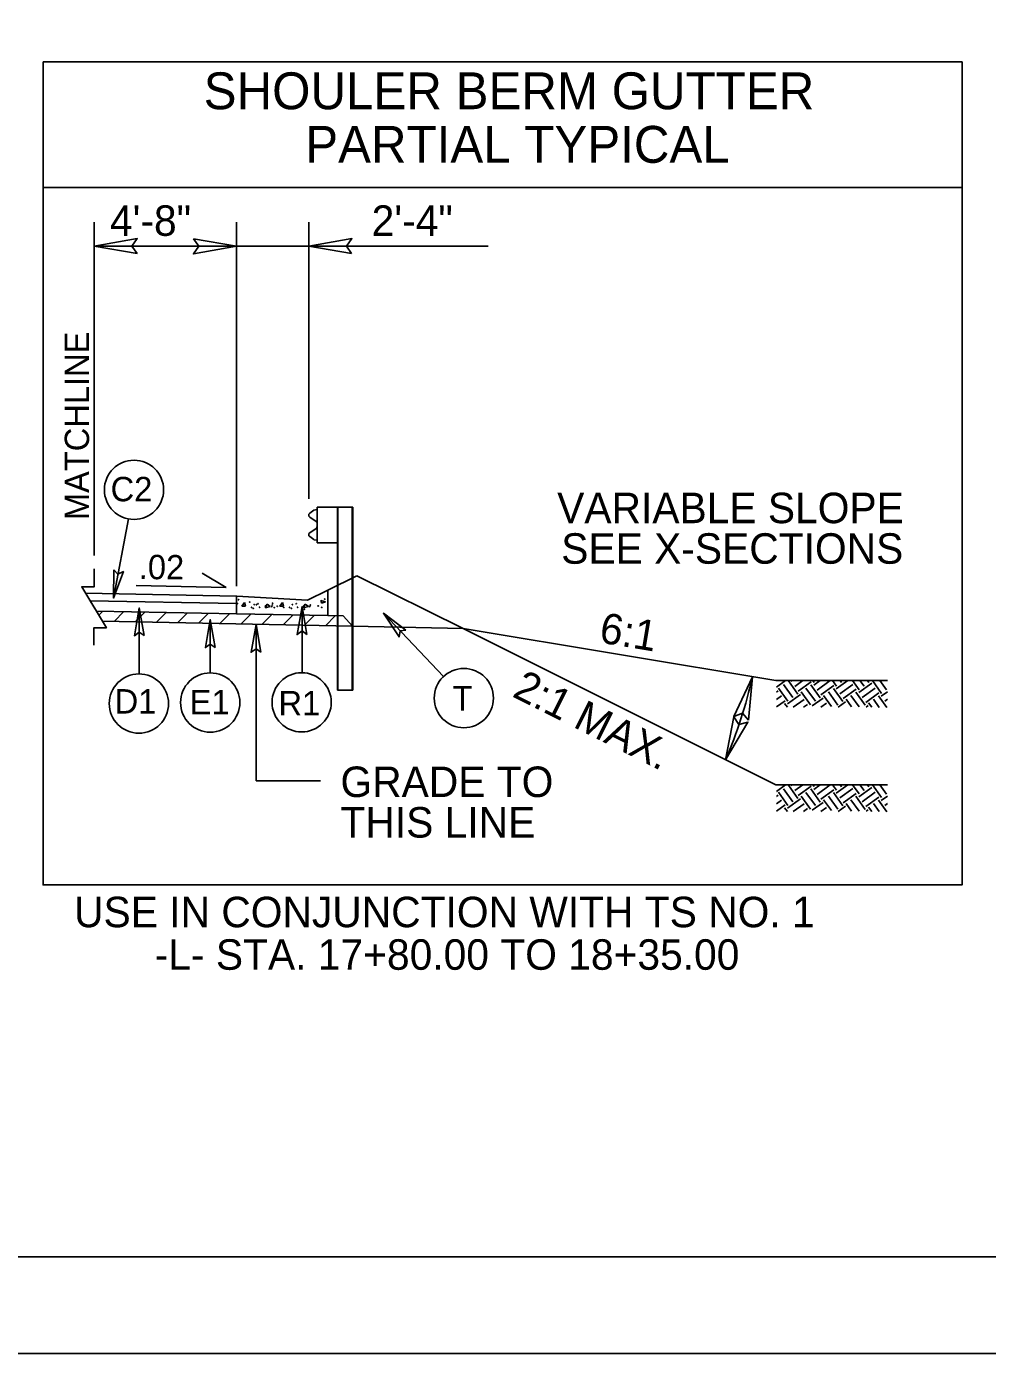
# Model space of a CAD drawing. Extents: x 1184121 to 1184397, y 1246506 to 1246661.
# Drawn here: x 1184220.23 to 1184251.75, y 1246505.71 to 1246549.22 of the extents above; entities that cross this region are included whole.
import ezdxf

# ---------------------------------------------------------------- set-up
doc = ezdxf.new("R2010")
doc.units = 0
for name, color, linetype in [('P_RDY_DXS_Guardrail_Cell', 7, 'Continuous'), ('Prop Shade Light', 7, 'Continuous'), ('Sheet Data Field CELL', 7, 'Continuous'), ('Sheet Plan CELL', 7, 'Continuous'), ('Sheet Plot Border Outside CELL', 7, 'Continuous'), ('Typical Text Label CELL', 7, 'Continuous'), ('z - Construction', 7, 'Continuous')]:
    doc.layers.add(name, color=color, linetype=linetype)

msp = doc.modelspace()

# ---------------------------------------------------------------- linework, layer by layer
at = {"layer": 'P_RDY_DXS_Guardrail_Cell'}
for p, q in [((1184229.654, 1246533.361), (1184229.517, 1246533.264)), ((1184229.754, 1246533.382), (1184229.667, 1246533.367)), ((1184230.427, 1246533.462), (1184229.76, 1246533.462)), ((1184229.76, 1246533.462), (1184229.76, 1246532.296)), ((1184230.427, 1246533.462), (1184230.927, 1246533.462)), ((1184230.443, 1246533.462), (1184230.427, 1246533.462)), ((1184230.427, 1246533.462), (1184230.427, 1246527.462)), ((1184230.443, 1246527.462), (1184230.443, 1246533.462)), ((1184230.927, 1246533.462), (1184230.911, 1246533.462)), ((1184230.911, 1246533.462), (1184230.911, 1246527.462)), ((1184230.927, 1246527.462), (1184230.927, 1246533.462)), ((1184229.518, 1246533.135), (1184229.726, 1246532.991)), ((1184229.76, 1246532.927), (1184229.76, 1246532.879)), ((1184229.76, 1246532.879), (1184229.76, 1246532.831)), ((1184229.517, 1246532.493), (1184229.654, 1246532.396)), ((1184229.726, 1246532.766), (1184229.518, 1246532.623)), ((1184229.667, 1246532.391), (1184229.754, 1246532.375)), ((1184229.76, 1246532.296), (1184230.427, 1246532.296)), ((1184230.427, 1246527.462), (1184230.927, 1246527.462)), ((1184230.427, 1246527.462), (1184230.443, 1246527.462)), ((1184230.911, 1246527.462), (1184230.927, 1246527.462))]:
    msp.add_line(p, q, dxfattribs=at)
for centre, radius, start, end in [((1184229.562, 1246533.2), 0.0787, 125.2976, 235.3478), ((1184229.673, 1246533.335), 0.0328, 100, 125.2976), ((1184229.681, 1246532.927), 0.0787, 0.02, 55.3478), ((1184229.681, 1246532.831), 0.0787, 304.6522, 359.98), ((1184229.562, 1246532.558), 0.0787, 124.6522, 234.7024), ((1184229.673, 1246532.423), 0.0328, 234.7024, 260)]:
    msp.add_arc(centre, radius, start, end, dxfattribs=at)
at = {"layer": 'Prop Shade Light'}
msp.add_lwpolyline([(1184227.114, 1246529.963), (1184222.518, 1246530.055), (1184222.315, 1246530.392), (1184227.109, 1246530.296), (1184227.114, 1246530.296)], close=True, dxfattribs=at)
at = {"layer": 'Sheet Data Field CELL'}
for p, q in [((1184222.447, 1246531.874), (1184222.447, 1246542.801)), ((1184227.114, 1246530.865), (1184227.114, 1246542.801)), ((1184229.484, 1246533.73), (1184229.484, 1246542.801)), ((1184222.447, 1246542.017), (1184227.114, 1246542.017)), ((1184227.114, 1246542.017), (1184235.365, 1246542.017)), ((1184223.079, 1246530.481), (1184223.574, 1246533.073)), ((1184226.776, 1246530.828), (1184225.993, 1246531.301)), ((1184231.065, 1246531.207), (1184230.114, 1246530.736)), ((1184231.065, 1246531.207), (1184234.553, 1246529.481)), ((1184222.163, 1246530.645), (1184227.114, 1246530.546)), ((1184226.776, 1246530.828), (1184223.822, 1246530.887)), ((1184229.447, 1246530.406), (1184230.114, 1246530.736)), ((1184230.114, 1246529.903), (1184230.114, 1246530.736)), ((1184222.315, 1246530.392), (1184227.109, 1246530.296)), ((1184227.114, 1246530.546), (1184227.114, 1246530.546)), ((1184227.114, 1246530.546), (1184227.114, 1246530.535)), ((1184227.114, 1246529.963), (1184227.114, 1246530.535)), ((1184227.125, 1246530.546), (1184229.447, 1246530.406)), ((1184227.292, 1246530.213), (1184227.378, 1246530.333)), ((1184227.412, 1246530.219), (1184227.292, 1246530.213)), ((1184227.378, 1246530.333), (1184227.412, 1246530.219)), ((1184228.057, 1246530.162), (1184228.12, 1246530.276)), ((1184228.223, 1246530.201), (1184228.057, 1246530.162)), ((1184228.12, 1246530.276), (1184228.223, 1246530.201)), ((1184228.541, 1246530.213), (1184228.627, 1246530.333)), ((1184228.661, 1246530.219), (1184228.541, 1246530.213)), ((1184228.627, 1246530.333), (1184228.661, 1246530.219)), ((1184229.265, 1246530.199), (1184229.265, 1246528.032)), ((1184229.306, 1246530.162), (1184229.368, 1246530.276)), ((1184229.471, 1246530.201), (1184229.306, 1246530.162)), ((1184229.368, 1246530.276), (1184229.471, 1246530.201)), ((1184229.884, 1246530.405), (1184229.9, 1246530.314)), ((1184230.038, 1246530.36), (1184229.884, 1246530.405)), ((1184229.9, 1246530.314), (1184230.038, 1246530.36)), ((1184222.518, 1246530.055), (1184227.114, 1246529.963)), ((1184222.599, 1246529.919), (1184222.73, 1246530.05)), ((1184223.096, 1246529.71), (1184223.423, 1246530.036)), ((1184223.79, 1246529.696), (1184224.116, 1246530.023)), ((1184223.926, 1246530.158), (1184223.926, 1246527.991)), ((1184224.483, 1246529.682), (1184224.809, 1246530.009)), ((1184225.176, 1246529.668), (1184225.503, 1246529.995)), ((1184225.869, 1246529.654), (1184226.196, 1246529.981)), ((1184226.253, 1246529.772), (1184226.253, 1246528.026)), ((1184226.563, 1246529.641), (1184226.889, 1246529.967)), ((1184230.114, 1246529.903), (1184227.114, 1246529.963)), ((1184227.256, 1246529.627), (1184227.582, 1246529.953)), ((1184227.949, 1246529.613), (1184228.276, 1246529.939)), ((1184228.642, 1246529.599), (1184228.969, 1246529.926)), ((1184229.336, 1246529.585), (1184229.662, 1246529.912)), ((1184230.029, 1246529.571), (1184230.356, 1246529.898)), ((1184230.114, 1246529.903), (1184230.614, 1246529.893)), ((1184230.614, 1246529.893), (1184230.923, 1246529.553)), ((1184231.934, 1246529.979), (1184233.903, 1246527.905)), ((1184222.72, 1246529.717), (1184230.923, 1246529.553)), ((1184227.754, 1246529.617), (1184227.754, 1246524.484)), ((1184230.923, 1246529.553), (1184234.553, 1246529.481)), ((1184234.553, 1246529.481), (1184244.81, 1246527.771)), ((1184234.553, 1246529.481), (1184244.81, 1246524.352)), ((1184244.81, 1246527.771), (1184248.464, 1246527.771)), ((1184244.81, 1246527.771), (1184248.464, 1246527.771)), ((1184244.824, 1246527.559), (1184245.119, 1246527.772)), ((1184244.824, 1246527.559), (1184245.119, 1246527.772)), ((1184245.364, 1246527.214), (1184245.055, 1246527.644)), ((1184245.364, 1246527.214), (1184245.055, 1246527.644)), ((1184245.525, 1246527.33), (1184245.216, 1246527.76)), ((1184245.525, 1246527.33), (1184245.216, 1246527.76)), ((1184245.308, 1246527.745), (1184245.347, 1246527.772)), ((1184245.308, 1246527.745), (1184245.347, 1246527.772)), ((1184245.424, 1246527.583), (1184245.688, 1246527.773)), ((1184245.424, 1246527.583), (1184245.688, 1246527.773)), ((1184245.54, 1246527.422), (1184245.969, 1246527.731)), ((1184245.54, 1246527.422), (1184245.969, 1246527.731)), ((1184246.263, 1246527.209), (1184245.954, 1246527.639)), ((1184246.263, 1246527.209), (1184245.954, 1246527.639)), ((1184246.062, 1246527.716), (1184246.02, 1246527.774)), ((1184246.062, 1246527.716), (1184246.02, 1246527.774)), ((1184246.047, 1246527.624), (1184246.257, 1246527.775)), ((1184246.047, 1246527.624), (1184246.257, 1246527.775)), ((1184246.162, 1246527.463), (1184246.592, 1246527.771)), ((1184246.162, 1246527.463), (1184246.592, 1246527.771)), ((1184246.278, 1246527.301), (1184246.708, 1246527.61)), ((1184246.278, 1246527.301), (1184246.708, 1246527.61)), ((1184246.8, 1246527.595), (1184246.67, 1246527.776)), ((1184246.8, 1246527.595), (1184246.67, 1246527.776)), ((1184246.785, 1246527.503), (1184247.168, 1246527.778)), ((1184246.785, 1246527.503), (1184247.168, 1246527.778)), ((1184246.901, 1246527.342), (1184247.331, 1246527.65)), ((1184246.901, 1246527.342), (1184247.331, 1246527.65)), ((1184246.961, 1246527.711), (1184246.914, 1246527.777)), ((1184246.961, 1246527.711), (1184246.914, 1246527.777)), ((1184247.539, 1246527.474), (1184247.325, 1246527.771)), ((1184247.539, 1246527.474), (1184247.325, 1246527.771)), ((1184247.523, 1246527.382), (1184247.953, 1246527.691)), ((1184247.523, 1246527.382), (1184247.953, 1246527.691)), ((1184247.7, 1246527.59), (1184247.564, 1246527.779)), ((1184247.7, 1246527.59), (1184247.564, 1246527.779)), ((1184247.861, 1246527.706), (1184247.814, 1246527.771)), ((1184247.861, 1246527.706), (1184247.814, 1246527.771)), ((1184248.277, 1246527.353), (1184247.977, 1246527.771)), ((1184248.277, 1246527.353), (1184247.977, 1246527.771)), ((1184248.438, 1246527.469), (1184248.221, 1246527.771)), ((1184248.438, 1246527.469), (1184248.221, 1246527.771)), ((1184244.824, 1246527.396), (1184244.879, 1246527.436)), ((1184244.824, 1246527.396), (1184244.879, 1246527.436)), ((1184244.824, 1246527.152), (1184244.994, 1246527.275)), ((1184244.824, 1246527.152), (1184244.994, 1246527.275)), ((1184245.202, 1246527.098), (1184244.894, 1246527.528)), ((1184245.202, 1246527.098), (1184244.894, 1246527.528)), ((1184245.187, 1246527.006), (1184245.617, 1246527.315)), ((1184245.187, 1246527.006), (1184245.617, 1246527.315)), ((1184245.375, 1246526.897), (1184245.733, 1246527.154)), ((1184245.375, 1246526.897), (1184245.733, 1246527.154)), ((1184245.941, 1246526.978), (1184245.632, 1246527.407)), ((1184245.941, 1246526.978), (1184245.632, 1246527.407)), ((1184246.102, 1246527.093), (1184245.793, 1246527.523)), ((1184246.102, 1246527.093), (1184245.793, 1246527.523)), ((1184246.003, 1246526.94), (1184246.355, 1246527.194)), ((1184246.003, 1246526.94), (1184246.355, 1246527.194)), ((1184246.628, 1246526.928), (1184246.371, 1246527.286)), ((1184246.628, 1246526.928), (1184246.371, 1246527.286)), ((1184246.84, 1246526.972), (1184246.532, 1246527.402)), ((1184246.84, 1246526.972), (1184246.532, 1246527.402)), ((1184247.002, 1246527.088), (1184246.693, 1246527.518)), ((1184247.002, 1246527.088), (1184246.693, 1246527.518)), ((1184247.017, 1246527.181), (1184247.446, 1246527.489)), ((1184247.017, 1246527.181), (1184247.446, 1246527.489)), ((1184247.289, 1246526.915), (1184247.109, 1246527.165)), ((1184247.289, 1246526.915), (1184247.109, 1246527.165)), ((1184247.537, 1246526.91), (1184247.27, 1246527.281)), ((1184247.537, 1246526.91), (1184247.27, 1246527.281)), ((1184247.74, 1246526.967), (1184247.431, 1246527.397)), ((1184247.74, 1246526.967), (1184247.431, 1246527.397)), ((1184247.639, 1246527.221), (1184248.069, 1246527.53)), ((1184247.639, 1246527.221), (1184248.069, 1246527.53)), ((1184247.755, 1246527.06), (1184248.185, 1246527.368)), ((1184247.755, 1246527.06), (1184248.185, 1246527.368)), ((1184248.198, 1246526.896), (1184248.008, 1246527.16)), ((1184248.198, 1246526.896), (1184248.008, 1246527.16)), ((1184248.446, 1246526.891), (1184248.17, 1246527.276)), ((1184248.446, 1246526.891), (1184248.17, 1246527.276)), ((1184248.262, 1246527.261), (1184248.464, 1246527.406)), ((1184248.262, 1246527.261), (1184248.464, 1246527.406)), ((1184248.378, 1246527.1), (1184248.464, 1246527.162)), ((1184248.378, 1246527.1), (1184248.464, 1246527.162)), ((1184244.824, 1246526.908), (1184245.11, 1246527.114)), ((1184244.824, 1246526.908), (1184245.11, 1246527.114)), ((1184245.184, 1246526.897), (1184245.095, 1246527.021)), ((1184245.184, 1246526.897), (1184245.095, 1246527.021)), ((1184245.715, 1246526.897), (1184245.849, 1246526.993)), ((1184245.715, 1246526.897), (1184245.849, 1246526.993)), ((1184246.282, 1246526.897), (1184246.471, 1246527.033)), ((1184246.282, 1246526.897), (1184246.471, 1246527.033)), ((1184246.848, 1246526.897), (1184247.094, 1246527.073)), ((1184246.848, 1246526.897), (1184247.094, 1246527.073)), ((1184247.767, 1246526.905), (1184247.832, 1246526.952)), ((1184247.767, 1246526.905), (1184247.832, 1246526.952)), ((1184247.95, 1246526.901), (1184247.847, 1246527.045)), ((1184247.95, 1246526.901), (1184247.847, 1246527.045)), ((1184229.871, 1246524.484), (1184227.754, 1246524.484)), ((1184244.81, 1246524.352), (1184248.464, 1246524.352)), ((1184244.81, 1246524.352), (1184248.464, 1246524.352)), ((1184244.824, 1246524.14), (1184245.119, 1246524.353)), ((1184244.824, 1246524.14), (1184245.119, 1246524.353)), ((1184245.202, 1246523.679), (1184244.894, 1246524.109)), ((1184245.202, 1246523.679), (1184244.894, 1246524.109)), ((1184245.364, 1246523.795), (1184245.055, 1246524.225)), ((1184245.364, 1246523.795), (1184245.055, 1246524.225)), ((1184245.525, 1246523.911), (1184245.216, 1246524.341)), ((1184245.525, 1246523.911), (1184245.216, 1246524.341)), ((1184245.308, 1246524.325), (1184245.347, 1246524.353)), ((1184245.308, 1246524.325), (1184245.347, 1246524.353)), ((1184245.424, 1246524.164), (1184245.688, 1246524.354)), ((1184245.424, 1246524.164), (1184245.688, 1246524.354)), ((1184245.54, 1246524.003), (1184245.969, 1246524.312)), ((1184245.54, 1246524.003), (1184245.969, 1246524.312)), ((1184246.102, 1246523.674), (1184245.793, 1246524.104)), ((1184246.102, 1246523.674), (1184245.793, 1246524.104)), ((1184246.263, 1246523.79), (1184245.954, 1246524.22)), ((1184246.263, 1246523.79), (1184245.954, 1246524.22)), ((1184246.062, 1246524.297), (1184246.02, 1246524.355)), ((1184246.062, 1246524.297), (1184246.02, 1246524.355)), ((1184246.047, 1246524.205), (1184246.257, 1246524.356)), ((1184246.047, 1246524.205), (1184246.257, 1246524.356)), ((1184246.162, 1246524.043), (1184246.592, 1246524.352)), ((1184246.162, 1246524.043), (1184246.592, 1246524.352)), ((1184246.278, 1246523.882), (1184246.708, 1246524.191)), ((1184246.278, 1246523.882), (1184246.708, 1246524.191)), ((1184246.8, 1246524.176), (1184246.67, 1246524.357)), ((1184246.8, 1246524.176), (1184246.67, 1246524.357)), ((1184247.002, 1246523.669), (1184246.693, 1246524.099)), ((1184247.002, 1246523.669), (1184246.693, 1246524.099)), ((1184246.785, 1246524.084), (1184247.168, 1246524.359)), ((1184246.785, 1246524.084), (1184247.168, 1246524.359)), ((1184246.901, 1246523.923), (1184247.331, 1246524.231)), ((1184246.901, 1246523.923), (1184247.331, 1246524.231)), ((1184246.961, 1246524.292), (1184246.914, 1246524.358)), ((1184246.961, 1246524.292), (1184246.914, 1246524.358)), ((1184247.539, 1246524.055), (1184247.325, 1246524.352)), ((1184247.539, 1246524.055), (1184247.325, 1246524.352)), ((1184247.523, 1246523.963), (1184247.953, 1246524.272)), ((1184247.523, 1246523.963), (1184247.953, 1246524.272)), ((1184247.7, 1246524.171), (1184247.564, 1246524.36)), ((1184247.7, 1246524.171), (1184247.564, 1246524.36)), ((1184247.639, 1246523.802), (1184248.069, 1246524.11)), ((1184247.639, 1246523.802), (1184248.069, 1246524.11)), ((1184247.861, 1246524.287), (1184247.814, 1246524.352)), ((1184247.861, 1246524.287), (1184247.814, 1246524.352)), ((1184248.277, 1246523.934), (1184247.977, 1246524.352)), ((1184248.277, 1246523.934), (1184247.977, 1246524.352)), ((1184248.438, 1246524.05), (1184248.221, 1246524.352)), ((1184248.438, 1246524.05), (1184248.221, 1246524.352)), ((1184244.824, 1246523.977), (1184244.879, 1246524.017)), ((1184244.824, 1246523.977), (1184244.879, 1246524.017)), ((1184244.824, 1246523.733), (1184244.994, 1246523.856)), ((1184244.824, 1246523.733), (1184244.994, 1246523.856)), ((1184244.824, 1246523.489), (1184245.11, 1246523.694)), ((1184244.824, 1246523.489), (1184245.11, 1246523.694)), ((1184245.187, 1246523.587), (1184245.617, 1246523.896)), ((1184245.187, 1246523.587), (1184245.617, 1246523.896)), ((1184245.375, 1246523.478), (1184245.733, 1246523.735)), ((1184245.375, 1246523.478), (1184245.733, 1246523.735)), ((1184245.941, 1246523.558), (1184245.632, 1246523.988)), ((1184245.941, 1246523.558), (1184245.632, 1246523.988)), ((1184246.003, 1246523.521), (1184246.355, 1246523.775)), ((1184246.003, 1246523.521), (1184246.355, 1246523.775)), ((1184246.628, 1246523.509), (1184246.371, 1246523.867)), ((1184246.628, 1246523.509), (1184246.371, 1246523.867)), ((1184246.84, 1246523.553), (1184246.532, 1246523.983)), ((1184246.84, 1246523.553), (1184246.532, 1246523.983)), ((1184246.848, 1246523.478), (1184247.094, 1246523.654)), ((1184246.848, 1246523.478), (1184247.094, 1246523.654)), ((1184247.017, 1246523.761), (1184247.446, 1246524.07)), ((1184247.017, 1246523.761), (1184247.446, 1246524.07)), ((1184247.289, 1246523.495), (1184247.109, 1246523.746)), ((1184247.289, 1246523.495), (1184247.109, 1246523.746)), ((1184247.537, 1246523.491), (1184247.27, 1246523.862)), ((1184247.537, 1246523.491), (1184247.27, 1246523.862)), ((1184247.74, 1246523.548), (1184247.431, 1246523.978)), ((1184247.74, 1246523.548), (1184247.431, 1246523.978)), ((1184247.755, 1246523.641), (1184248.185, 1246523.949)), ((1184247.755, 1246523.641), (1184248.185, 1246523.949)), ((1184248.198, 1246523.477), (1184248.008, 1246523.741)), ((1184248.198, 1246523.477), (1184248.008, 1246523.741)), ((1184248.446, 1246523.472), (1184248.17, 1246523.857)), ((1184248.446, 1246523.472), (1184248.17, 1246523.857)), ((1184248.262, 1246523.842), (1184248.464, 1246523.987)), ((1184248.262, 1246523.842), (1184248.464, 1246523.987)), ((1184248.378, 1246523.681), (1184248.464, 1246523.743)), ((1184248.378, 1246523.681), (1184248.464, 1246523.743)), ((1184245.184, 1246523.478), (1184245.095, 1246523.602)), ((1184245.184, 1246523.478), (1184245.095, 1246523.602)), ((1184245.715, 1246523.478), (1184245.849, 1246523.574)), ((1184245.715, 1246523.478), (1184245.849, 1246523.574)), ((1184246.282, 1246523.478), (1184246.471, 1246523.614)), ((1184246.282, 1246523.478), (1184246.471, 1246523.614)), ((1184247.767, 1246523.486), (1184247.832, 1246523.533)), ((1184247.767, 1246523.486), (1184247.832, 1246523.533)), ((1184247.95, 1246523.482), (1184247.847, 1246523.625)), ((1184247.95, 1246523.482), (1184247.847, 1246523.625))]:
    msp.add_line(p, q, dxfattribs=at)
for points in [[(1184223.853, 1246541.775), (1184222.447, 1246542.017), (1184223.861, 1246542.267), (1184223.681, 1246542.017)], [(1184225.708, 1246542.259), (1184227.114, 1246542.017), (1184225.7, 1246541.767), (1184225.88, 1246542.017)], [(1184230.89, 1246541.775), (1184229.484, 1246542.017), (1184230.898, 1246542.267), (1184230.718, 1246542.017)], [(1184223.092, 1246531.404), (1184223.079, 1246530.481), (1184223.406, 1246531.35), (1184223.225, 1246531.266)], [(1184229.422, 1246529.289), (1184229.265, 1246530.199), (1184229.103, 1246529.284), (1184229.265, 1246529.4)], [(1184224.082, 1246529.248), (1184223.926, 1246530.158), (1184223.764, 1246529.243), (1184223.926, 1246529.359)], [(1184226.41, 1246528.862), (1184226.253, 1246529.772), (1184226.092, 1246528.857), (1184226.253, 1246528.973)], [(1184232.674, 1246529.427), (1184231.934, 1246529.979), (1184232.446, 1246529.204), (1184232.484, 1246529.4)], [(1184227.91, 1246528.707), (1184227.754, 1246529.617), (1184227.592, 1246528.702), (1184227.754, 1246528.818)], [(1184243.904, 1246526.479), (1184244.04, 1246527.9), (1184243.428, 1246526.601), (1184243.716, 1246526.709)], [(1184243.428, 1246526.58), (1184243.155, 1246525.179), (1184243.891, 1246526.413), (1184243.593, 1246526.333)]]:
    msp.add_lwpolyline(points, close=True, dxfattribs=at)
msp.add_lwpolyline([(1184222.447, 1246531.438), (1184222.447, 1246530.849), (1184222.04, 1246530.849), (1184222.847, 1246529.506), (1184222.439, 1246529.506), (1184222.439, 1246528.932)], dxfattribs=at)
for centre, radius in [((1184223.752, 1246534.029), 0.972), ((1184227.144, 1246530.3), 0.00802), ((1184227.182, 1246530.425), 0.00802), ((1184227.549, 1246530.35), 0.00802), ((1184227.608, 1246530.172), 0.00802), ((1184227.697, 1246530.265), 0.00802), ((1184227.773, 1246530.263), 0.00802), ((1184227.823, 1246530.293), 0.00802), ((1184227.87, 1246530.178), 0.00802), ((1184228.064, 1246530.217), 0.00802), ((1184228.27, 1246530.201), 0.00802), ((1184228.287, 1246530.251), 0.00802), ((1184228.297, 1246530.31), 0.00802), ((1184228.354, 1246530.168), 0.00802), ((1184228.45, 1246530.213), 0.00802), ((1184228.544, 1246530.223), 0.00802), ((1184228.663, 1246530.172), 0.00802), ((1184228.858, 1246530.172), 0.00802), ((1184228.947, 1246530.265), 0.00802), ((1184229.072, 1246530.293), 0.00802), ((1184229.119, 1246530.178), 0.00802), ((1184229.313, 1246530.217), 0.00802), ((1184229.519, 1246530.201), 0.00802), ((1184229.536, 1246530.251), 0.00802), ((1184229.793, 1246530.223), 0.00802), ((1184229.913, 1246530.172), 0.00802), ((1184230.01, 1246530.445), 0.00802), ((1184227.664, 1246530.138), 0.00802), ((1184228.914, 1246530.138), 0.00802), ((1184229.342, 1246530.115), 0.00802), ((1184226.252, 1246527.054), 0.972), ((1184229.251, 1246527.06), 0.972), ((1184234.572, 1246527.2), 0.972), ((1184223.912, 1246527.019), 0.972)]:
    msp.add_circle(centre, radius, dxfattribs=at)
for centre, radius, start, end in [((1184227.124, 1246530.535), 0.0104, 87.952, 180), ((1184229.398, 1246531.157), 15, 336.5152, 347.4573)]:
    msp.add_arc(centre, radius, start, end, dxfattribs=at)
at = {"layer": 'Sheet Plan CELL'}
msp.add_line((1184126.181, 1246508.875), (1184358.419, 1246508.875), dxfattribs=at)
at = {"layer": 'Sheet Plot Border Outside CELL'}
msp.add_lwpolyline([(1184121.05, 1246660.53), (1184360.324, 1246660.53), (1184360.324, 1246505.708), (1184121.05, 1246505.708)], close=True, dxfattribs=at)
at = {"layer": 'Typical Text Label CELL'}
msp.add_line((1184220.767, 1246543.939), (1184250.918, 1246543.939), dxfattribs=at)
msp.add_lwpolyline([(1184220.767, 1246548.062), (1184250.918, 1246548.062), (1184250.918, 1246521.07), (1184220.767, 1246521.07)], close=True, dxfattribs=at)
at = {"layer": 'z - Construction'}
msp.add_line((1184121.05, 1246505.708), (1184360.324, 1246505.708), dxfattribs=at)

# ---------------------------------------------------------------- texts
at = {"layer": 'Sheet Data Field CELL'}
for s, height, p in [('SHOULER BERM GUTTER', 1.20892, (1184226.037, 1246546.51)), ('PARTIAL TYPICAL', 1.20892, (1184229.369, 1246544.753)), ('C2', 0.8, (1184222.985, 1246533.653)), ('D1', 0.8, (1184223.118, 1246526.693)), ('E1', 0.8, (1184225.58, 1246526.669)), ('R1', 0.8, (1184228.491, 1246526.635)), ('GRADE TO ', 1, (1184230.525, 1246523.955)), ('THIS LINE', 1, (1184230.525, 1246522.625))]:
    msp.add_text(s, height=height, dxfattribs=at).set_placement(p)
for s, height, rotation, p in [('4\'-8"', 1, 359.9998, (1184222.963, 1246542.358)), ('2\'-4"', 1, 359.9998, (1184231.548, 1246542.358)), ('MATCHLINE', 0.8, 90, (1184222.279, 1246533.035)), ('VARIABLE SLOPE', 1, 360, (1184237.633, 1246532.935)), ('SEE X-SECTIONS', 1, 360, (1184237.766, 1246531.605)), ('.02', 0.8, 359.4598, (1184223.907, 1246531.102)), ('6:1', 1, 350.5375, (1184238.98, 1246529.03)), ('2:1 MAX.', 1, 333.4348, (1184236.125, 1246527.265)), ('T', 0.8, 359.9997, (1184234.203, 1246526.792)), ('USE IN CONJUNCTION WITH TS NO. 1', 1, 0.0002, (1184221.787, 1246519.685)), ('-L- STA. 17+80.00 TO 18+35.00', 1, 0.0002, (1184224.432, 1246518.29))]:
    msp.add_text(s, height=height, rotation=rotation, dxfattribs=at).set_placement(p)

doc.saveas('drawing.dxf')
